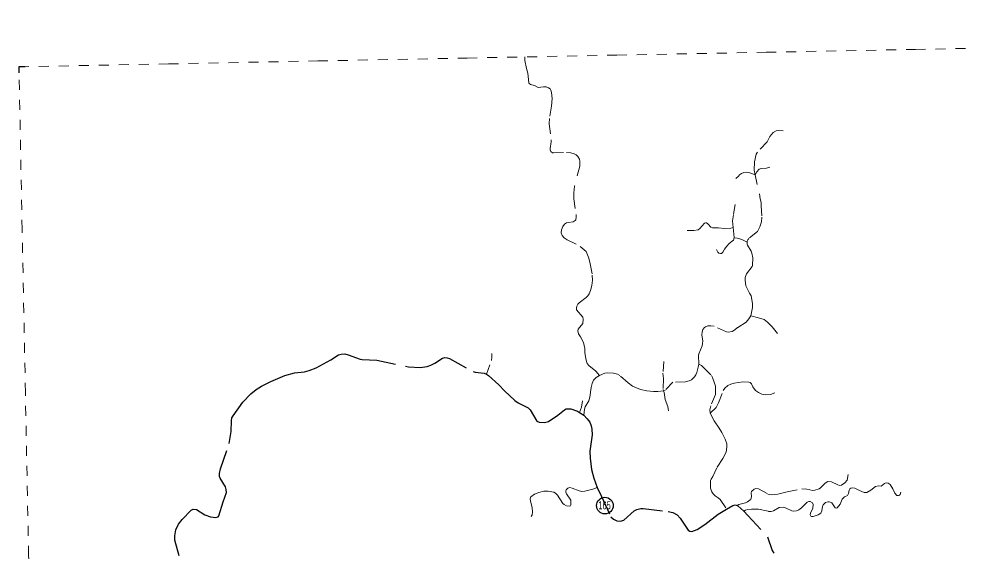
# Model space of a CAD drawing. Extents: x 220.8 to 246.7, y 7287.6 to 7315.8.
# Drawn here: x 220.75 to 230.23, y 7310.46 to 7315.78 of the extents above; entities that cross this region are included whole.
import ezdxf
from ezdxf.enums import TextEntityAlignment as Align

# ---------------------------------------------------------------- set-up
doc = ezdxf.new("R2010")
doc.units = 0
doc.header["$LTSCALE"] = 0.032
for name, pattern in [('DOTTED', [1.5, 0.3, -1.2]), ('LONG_DASHED', [7.5, 6, -1.5]), ('MEDIUM_DASHED', [4.5, 3, -1.5]), ('SHORT_DASHED', [2.7, 1.5, -1.2])]:
    doc.linetypes.add(name, pattern=pattern)
for name, color, linetype, lineweight in [('13', 7, 'Continuous', 25), ('35', 7, 'SHORT_DASHED', 13), ('4', 7, 'LONG_DASHED', 25), ('6', 7, 'MEDIUM_DASHED', 13), ('63', 7, 'Continuous', 25), ('7', 7, 'DOTTED', 13)]:
    doc.layers.add(name, color=color, linetype=linetype, lineweight=lineweight)
doc.layers.add('61', color=7, linetype='Continuous')

msp = doc.modelspace()

# ---------------------------------------------------------------- linework, layer by layer
at = {"layer": '13'}
msp.add_circle((226.6119, 7310.9192), 0.083, dxfattribs=at)
at = {"layer": '35'}
for points in [[(220.7543, 7315.3049), (222.2482, 7315.3343), (223.7422, 7315.3636), (225.2361, 7315.3926), (226.7301, 7315.4216), (228.224, 7315.4503), (229.718, 7315.4789), (231.2119, 7315.5074), (232.7059, 7315.5357), (234.1998, 7315.5638), (235.6938, 7315.5918), (237.1877, 7315.6196), (238.6817, 7315.6472), (240.1757, 7315.6748), (241.6697, 7315.7021), (243.1636, 7315.7293), (244.6576, 7315.7563), (246.1516, 7315.7832)], [(221.3035, 7287.6034), (221.271, 7289.2329), (221.2386, 7290.8624), (221.2062, 7292.4919), (221.1738, 7294.1214), (221.1414, 7295.7509), (221.109, 7297.3804), (221.0767, 7299.0099), (221.0443, 7300.6394), (221.0121, 7302.2689), (220.9798, 7303.8984), (220.9475, 7305.5279), (220.9153, 7307.1574), (220.883, 7308.7869), (220.8508, 7310.4164), (220.8187, 7312.0459), (220.7865, 7313.6754), (220.7543, 7315.3049)]]:
    msp.add_lwpolyline(points, dxfattribs=at)
at = {"layer": '4'}
for points in [[(222.3557, 7310.418), (222.3116, 7310.5721), (222.3116, 7310.6161), (222.3239, 7310.6773), (222.3508, 7310.7323), (222.3875, 7310.7813), (222.4755, 7310.8742), (222.4963, 7310.884), (222.5293, 7310.8791), (222.6125, 7310.8265), (222.6688, 7310.8082), (222.7241, 7310.7998), (222.7446, 7310.8069), (222.7519, 7310.8179), (222.7958, 7310.9569), (222.8282, 7311.0491), (222.8266, 7311.0797), (222.818, 7311.1066), (222.7654, 7311.1922), (222.7605, 7311.2093), (222.7593, 7311.2387), (222.7691, 7311.2876), (222.8571, 7311.5396), (222.8743, 7311.6582), (222.8779, 7311.7659), (222.884, 7311.7952), (222.895, 7311.816), (222.9929, 7311.953), (223.0712, 7312.0362), (223.1262, 7312.079), (223.1776, 7312.1132), (223.273, 7312.1585), (223.4136, 7312.2184), (223.5078, 7312.2478), (223.6106, 7312.2575), (223.6571, 7312.2698), (223.7255, 7312.2967), (223.8711, 7312.3774), (223.9481, 7312.4251), (223.9763, 7312.4337), (224.013, 7312.4349), (224.046, 7312.4263), (224.1646, 7312.3823), (224.1866, 7312.3786), (224.3322, 7312.3713), (224.6491, 7312.3061), (224.764, 7312.2979), (224.8361, 7312.3101), (224.8728, 7312.3224), (224.9132, 7312.3432), (224.9902, 7312.3933), (225.0122, 7312.3982), (225.0343, 7312.3958), (225.0575, 7312.3896), (225.2948, 7312.2588), (225.3156, 7312.2514), (225.4049, 7312.2416), (225.4274, 7312.2321), (225.4489, 7312.2208), (225.5529, 7312.1254), (225.6079, 7312.0667), (225.7119, 7311.9701), (225.7437, 7311.9469), (225.844, 7311.8979), (225.866, 7311.8772), (225.932, 7311.7634), (225.9553, 7311.7536), (226.0079, 7311.7487)], [(226.0079, 7311.7487), (226.0482, 7311.7597), (226.1412, 7311.8221), (226.2084, 7311.8767), (226.2244, 7311.8856), (226.2707, 7311.8856), (226.3369, 7311.8637), (226.3585, 7311.8501), (226.4021, 7311.8217), (226.4347, 7311.7879), (226.4604, 7311.7536), (226.4751, 7311.7157), (226.4812, 7311.6839), (226.4836, 7311.6264), (226.4616, 7311.4637), (226.4641, 7311.3916), (226.4788, 7311.2791), (226.5032, 7311.1934), (226.5353, 7311.1005), (226.5766, 7311.01), (226.672, 7310.8057), (226.6965, 7310.7825), (226.7319, 7310.7678), (226.7674, 7310.7641), (226.8004, 7310.7751), (226.9044, 7310.8656), (226.9325, 7310.8791), (226.9704, 7310.8901), (226.9961, 7310.8913), (227.2456, 7310.8608), (227.2921, 7310.851), (227.3337, 7310.8253), (227.3655, 7310.7923), (227.445, 7310.6748), (227.4621, 7310.6638), (227.4805, 7310.6614), (227.5343, 7310.6797), (227.6114, 7310.7287), (227.7434, 7310.8326), (227.8278, 7310.8842), (227.8923, 7310.9208), (227.9159, 7310.9256), (227.9355, 7310.9212), (227.9428, 7310.9182), (227.9996, 7310.8622), (228.0407, 7310.8216), (228.2364, 7310.6063), (228.2841, 7310.4718), (228.3012, 7310.4425)]]:
    msp.add_lwpolyline(points, dxfattribs=at)
at = {"layer": '6'}
for points in [[(225.8123, 7315.4038), (225.8129, 7315.3674), (225.8284, 7315.2896), (225.8414, 7315.2427), (225.8533, 7315.1424), (225.8687, 7315.1281), (225.9079, 7315.118), (225.937, 7315.1014), (225.9465, 7315.0996), (225.9999, 7315.1062), (226.0261, 7315.1032), (226.0492, 7315.0949), (226.0641, 7315.0836), (226.073, 7315.0711), (226.0795, 7315.0498), (226.0837, 7314.9874), (226.0789, 7314.9114), (226.0593, 7314.7879), (226.0564, 7314.7345), (226.0759, 7314.5748), (226.0765, 7314.554), (226.0664, 7314.4899), (226.0664, 7314.4738), (226.0724, 7314.4572), (226.0872, 7314.4453), (226.0997, 7314.4441), (226.228, 7314.4477), (226.2713, 7314.4447), (226.3057, 7314.4358), (226.3259, 7314.4239), (226.342, 7314.4073), (226.3568, 7314.3812), (226.361, 7314.3634), (226.3604, 7314.3123), (226.3099, 7314.1128), (226.3016, 7314.0451), (226.3004, 7313.9869), (226.3253, 7313.8296), (226.3259, 7313.8023), (226.3206, 7313.7756), (226.3152, 7313.7672), (226.295, 7313.7548), (226.2452, 7313.7488), (226.2285, 7313.7441), (226.2072, 7313.731), (226.1905, 7313.7097), (226.1787, 7313.6746), (226.1763, 7313.6467), (226.1858, 7313.6188), (226.2054, 7313.5968), (226.2345, 7313.5767), (226.3651, 7313.5096), (226.4233, 7313.4597), (226.4518, 7313.3932), (226.466, 7313.3356), (226.4862, 7313.2228), (226.4898, 7313.1717), (226.4821, 7313.1201), (226.4696, 7313.069), (226.4565, 7313.0363), (226.4417, 7313.0156), (226.4263, 7312.9983), (226.355, 7312.9449), (226.342, 7312.9324), (226.3313, 7312.9122), (226.3277, 7312.8944), (226.3295, 7312.8772), (226.3912, 7312.8036), (226.396, 7312.7822), (226.393, 7312.7383), (226.3449, 7312.6825), (226.3425, 7312.6652), (226.3473, 7312.635), (226.3675, 7312.6076), (226.3966, 7312.5495), (226.4108, 7312.4901), (226.4126, 7312.445), (226.4203, 7312.3897), (226.4275, 7312.3589), (226.4364, 7312.3381), (226.4506, 7312.3203), (226.5219, 7312.2639), (226.5581, 7312.2211)], [(228.174, 7313.9143), (228.1807, 7313.8014), (228.1762, 7313.7553), (228.1612, 7313.7047), (228.1363, 7313.6595), (228.052, 7313.5903), (228.0405, 7313.5761), (228.0343, 7313.561), (228.0343, 7313.5508), (228.0343, 7313.5326), (228.0378, 7313.522), (228.0733, 7313.4607), (228.0813, 7313.4412), (228.0911, 7313.3969), (228.0884, 7313.3197), (228.084, 7313.3099), (228.0263, 7313.2363), (228.0148, 7313.1981), (228.013, 7313.1733), (228.0219, 7313.1174), (228.0573, 7313.0428), (228.0733, 7313.0162), (228.0813, 7312.9807), (228.0875, 7312.9364), (228.0884, 7312.9), (228.0702, 7312.8172), (228.052, 7312.7873), (228.0254, 7312.7536), (227.9385, 7312.6986), (227.9109, 7312.6746), (227.8861, 7312.6586), (227.848, 7312.6515), (227.8284, 7312.6551), (227.7051, 7312.7119), (227.6714, 7312.7172), (227.6421, 7312.7163), (227.6173, 7312.7074), (227.6084, 7312.7003), (227.5924, 7312.6799), (227.5844, 7312.6551), (227.58, 7312.6232), (227.5906, 7312.5664), (227.5889, 7312.538), (227.5853, 7312.5149), (227.5525, 7312.4368), (227.5481, 7312.42), (227.5507, 7312.3339)], [(227.5507, 7312.3339), (227.5454, 7312.302), (227.5312, 7312.2496), (227.5206, 7312.2248), (227.5081, 7312.2061), (227.4771, 7312.176), (227.4531, 7312.1653), (227.4176, 7312.1573), (227.2899, 7312.1529), (227.2153, 7312.0704), (227.1985, 7312.0663), (227.1399, 7312.0597), (227.0982, 7312.0606), (227.0308, 7312.0651), (226.9669, 7312.0784), (226.8897, 7312.1121), (226.8445, 7312.1467), (226.7619, 7312.2186), (226.7371, 7312.2336), (226.6998, 7312.2434), (226.6395, 7312.2461), (226.6129, 7312.2416), (226.5581, 7312.2211)], [(227.5507, 7312.3339), (227.5779, 7312.3183), (227.6026, 7312.2966), (227.6775, 7312.2202), (227.688, 7312.1999), (227.709, 7312.143), (227.7165, 7312.113), (227.7195, 7312.0621), (227.7165, 7312.0298), (227.6715, 7311.9174), (227.6618, 7311.8762), (227.6648, 7311.8425), (227.7038, 7311.7653), (227.754, 7311.6942), (227.7817, 7311.6484), (227.8139, 7311.5848), (227.8311, 7311.5376), (227.8326, 7311.5226), (227.8326, 7311.5016), (227.8229, 7311.4536), (227.7899, 7311.3884), (227.73, 7311.2963), (227.691, 7311.2109), (227.6745, 7311.1846), (227.6693, 7311.1704), (227.6663, 7311.1472), (227.6693, 7311.0947), (227.6798, 7311.058), (227.6933, 7311.037), (227.7142, 7311.0175), (227.7457, 7310.9966), (227.7629, 7310.9786), (227.8278, 7310.8842)], [(226.5581, 7312.2211), (226.5242, 7312.2009), (226.4981, 7312.1718), (226.4839, 7312.1392), (226.4755, 7312.1), (226.4619, 7312.0038), (226.4506, 7311.9676), (226.4138, 7311.9058), (226.4073, 7311.8844), (226.4021, 7311.8217)]]:
    msp.add_lwpolyline(points, dxfattribs=at)
at = {"layer": '63'}
msp.add_lwpolyline([(220.8159, 7315.3049), (220.7543, 7315.3049), (220.7543, 7315.2442)], dxfattribs=at)
at = {"layer": '7'}
msp.add_line((227.8958, 7313.6981), (227.9058, 7313.5952), dxfattribs=at)
for points in [[(228.3945, 7314.6634), (228.3477, 7314.6675), (228.3243, 7314.6643), (228.2933, 7314.6477), (228.2609, 7314.6072), (228.2343, 7314.5554), (228.1362, 7314.4524), (228.125, 7314.4326), (228.107, 7314.3539), (228.1052, 7314.2711), (228.1131, 7314.2248)], [(228.1131, 7314.2248), (228.0597, 7314.2454), (228.0271, 7314.2523), (227.9999, 7314.2493), (227.9763, 7314.2384), (227.959, 7314.2261), (227.9467, 7314.2103), (227.921, 7314.1876)], [(228.2595, 7314.3031), (228.2279, 7314.2917), (228.1746, 7314.2888), (228.1559, 7314.2814), (228.1297, 7314.2557), (228.1131, 7314.2248)], [(228.1131, 7314.2248), (228.1574, 7314.0344), (228.1641, 7313.9849), (228.1731, 7313.948), (228.174, 7313.9143)], [(227.9157, 7313.93), (227.8963, 7313.8258), (227.8889, 7313.7664), (227.8958, 7313.6981)], [(227.4361, 7313.6696), (227.5013, 7313.6683), (227.5438, 7313.6757), (227.5624, 7313.6874), (227.6077, 7313.7416), (227.6219, 7313.7464), (227.6295, 7313.7451), (227.6404, 7313.737), (227.6696, 7313.7033), (227.6893, 7313.695), (227.7487, 7313.6957), (227.8032, 7313.6874), (227.8698, 7313.6924), (227.8958, 7313.6981)], [(227.9058, 7313.5952), (227.8973, 7313.5706), (227.8549, 7313.5405), (227.8301, 7313.5138), (227.8068, 7313.4824), (227.7907, 7313.4537), (227.7774, 7313.4403), (227.7673, 7313.4377), (227.7513, 7313.4423), (227.7406, 7313.4524), (227.7293, 7313.4797)], [(227.9058, 7313.5952), (227.934, 7313.593), (227.97, 7313.582), (227.9931, 7313.5735), (228.0343, 7313.5508)], [(228.0702, 7312.8172), (228.1494, 7312.7975), (228.2042, 7312.778), (228.238, 7312.7532), (228.2837, 7312.707), (228.3391, 7312.6398)], [(225.4274, 7312.2321), (225.4777, 7312.3684), (225.482, 7312.4029), (225.4814, 7312.4381)], [(227.2006, 7312.3609), (227.1926, 7312.2414), (227.197, 7312.19), (227.1938, 7312.0796), (227.1985, 7312.0663), (227.2058, 7312.0481), (227.2153, 7311.9804), (227.2424, 7311.9094), (227.248, 7311.8652)], [(227.6648, 7311.8425), (227.7249, 7311.9012), (227.7475, 7311.9447), (227.7953, 7312.0709), (227.8098, 7312.0927), (227.8409, 7312.1183), (227.8703, 7312.1324), (227.9053, 7312.1422), (227.9915, 7312.155), (228.0499, 7312.1545), (228.0644, 7312.1481), (228.0772, 7312.1353), (228.0913, 7312.1068), (228.1177, 7312.0709), (228.1467, 7312.0483), (228.1812, 7312.0334), (228.2201, 7312.0266), (228.2691, 7312.0296), (228.3096, 7312.0475)], [(226.3585, 7311.8501), (226.3794, 7311.904), (226.3889, 7311.967)], [(227.9355, 7310.9212), (227.9508, 7310.9291), (228.0193, 7310.9477), (228.0388, 7310.9567), (228.0648, 7310.9753), (228.0701, 7310.9805), (228.0788, 7311.0109), (228.0747, 7311.0475), (228.0788, 7311.0596), (228.1029, 7311.0819), (228.1201, 7311.0893), (228.147, 7311.0883), (228.2411, 7311.0346), (228.2754, 7311.0258), (228.3417, 7311.0327), (228.4358, 7311.0582), (228.5819, 7311.087), (228.6319, 7311.0819), (228.6899, 7311.0698), (228.7094, 7311.073), (228.7543, 7311.0874), (228.7687, 7311.0953), (228.8146, 7311.144), (228.8401, 7311.1588), (228.8781, 7311.1574), (228.9407, 7311.1254), (228.9569, 7311.1213), (228.9769, 7311.124), (229.0121, 7311.1477), (229.0339, 7311.1723), (229.0441, 7311.2316)], [(227.9996, 7310.8622), (228.0192, 7310.8733), (228.0419, 7310.8795), (228.0789, 7310.8833), (228.1471, 7310.8833), (228.2461, 7310.8618), (228.2758, 7310.8587), (228.2962, 7310.8656), (228.3552, 7310.8988), (228.3937, 7310.903), (228.4234, 7310.893), (228.4796, 7310.8664), (228.4966, 7310.8645), (228.5282, 7310.8668), (228.5509, 7310.8768), (228.5771, 7310.8957), (228.6356, 7310.9523), (228.6518, 7310.9585), (228.6649, 7310.9589), (228.6873, 7310.9473), (228.695, 7310.9296), (228.6896, 7310.8938), (228.6688, 7310.8429), (228.6653, 7310.8252), (228.6715, 7310.814), (228.6788, 7310.8098), (228.6938, 7310.8098), (228.7435, 7310.8275), (228.7701, 7310.8444), (228.7805, 7310.8652), (228.7886, 7310.9103), (228.7955, 7310.9257), (228.8187, 7310.9492), (228.841, 7310.9562), (228.8529, 7310.9566), (228.8734, 7310.9508), (228.8803, 7310.9465), (228.913, 7310.8972), (228.925, 7310.8934), (228.935, 7310.898), (228.9651, 7310.935), (228.9832, 7310.9843), (229.0059, 7311.0066), (229.0371, 7311.0213), (229.0491, 7311.0417), (229.0544, 7311.0721), (229.061, 7311.0852), (229.0695, 7311.0929), (229.0841, 7311.0968), (229.1107, 7311.0945), (229.1562, 7311.0698), (229.2047, 7311.0486), (229.2321, 7311.0517), (229.271, 7311.0741), (229.3176, 7311.1095), (229.3461, 7311.1161), (229.3738, 7311.1141), (229.4062, 7311.1392), (229.4155, 7311.1438), (229.4289, 7311.1453), (229.4451, 7311.143), (229.4632, 7311.1284), (229.4913, 7311.0856), (229.5098, 7311.0425), (229.5318, 7311.0209), (229.5484, 7311.019), (229.5588, 7311.0228), (229.5653, 7311.0313), (229.5703, 7311.0536)], [(225.8759, 7310.8099), (225.8856, 7310.8276), (225.8885, 7310.8538), (225.8839, 7310.8989), (225.8673, 7310.9628), (225.8651, 7310.9868), (225.8719, 7311.0079), (225.9067, 7311.0324), (225.9529, 7311.0512), (226.0014, 7311.0626), (226.0436, 7311.0644), (226.1018, 7311.0518), (226.1184, 7311.0427), (226.1395, 7311.0233), (226.1931, 7310.9405), (226.2051, 7310.9297), (226.2279, 7310.9166), (226.2576, 7310.9132), (226.2673, 7310.9166), (226.2719, 7310.924), (226.2701, 7310.9731), (226.2274, 7311.0353), (226.2217, 7311.0541), (226.2217, 7311.0649), (226.2262, 7311.0769), (226.2422, 7311.094), (226.2611, 7311.0986), (226.2857, 7311.0936), (226.354, 7311.0672), (226.3808, 7311.0615), (226.4116, 7311.0638), (226.4915, 7311.082), (226.5353, 7311.1005)]]:
    msp.add_lwpolyline(points, dxfattribs=at)

# ---------------------------------------------------------------- texts
at = {"layer": '61', "width": 0.7}
msp.add_text('165', height=0.08, dxfattribs=at).set_placement((226.6088, 7310.8822), align=Align.CENTER)

doc.saveas('drawing.dxf')
